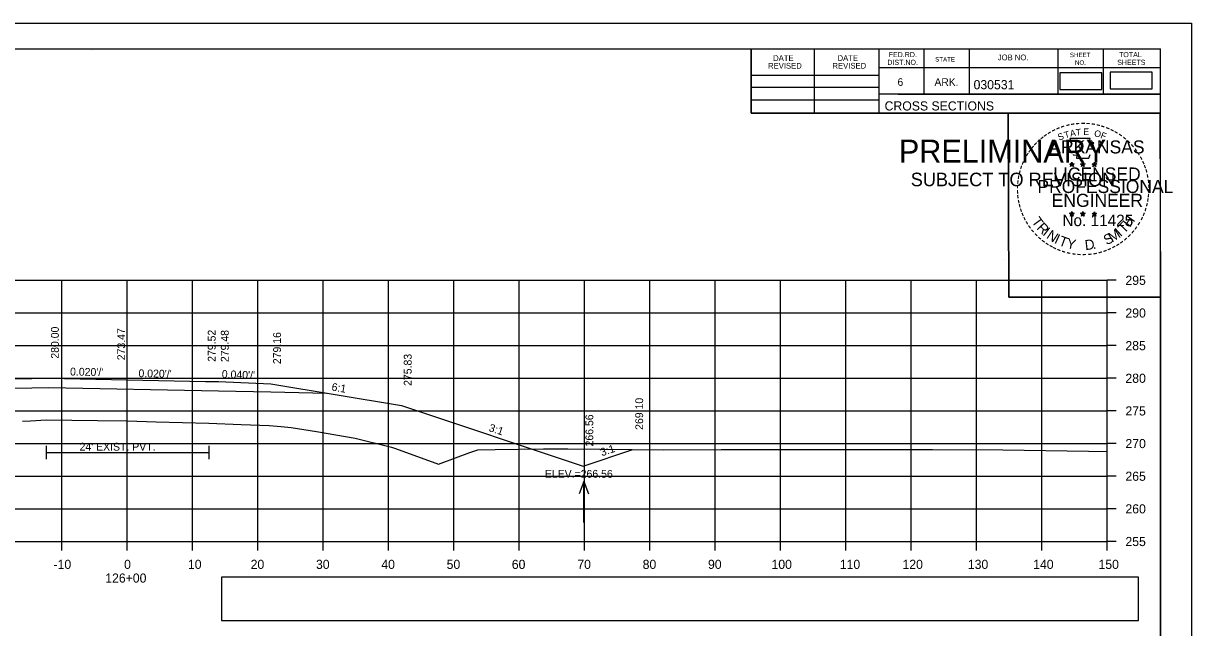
# Model space of a CAD drawing. Extents: x 285 to 4233, y -659 to 3710.
# Drawn here: x 2543.6 to 2722.4, y 1377 to 1469.5 of the extents above; entities that cross this region are included whole.
import ezdxf

# ---------------------------------------------------------------- set-up
doc = ezdxf.new("R2010")
doc.units = 0
for name, color, linetype in [('R_Alt Surface', 7, 'Continuous'), ('R_Axis', 7, 'Continuous'), ('R_Axis Annot', 7, 'Continuous'), ('R_Border', 7, 'Continuous'), ('R_Border PE', 7, 'Continuous'), ('R_Border Prem', 7, 'Continuous'), ('R_Exist Surface', 7, 'Continuous'), ('R_Fin Surface', 7, 'Continuous'), ('R_Grid', 7, 'Continuous'), ('R_No Plot', 7, 'Continuous'), ('R_Water', 7, 'Continuous'), ('R_Water Annot', 7, 'Continuous'), ('R_Xsect Elev', 7, 'Continuous'), ('R_Xsect Slope', 7, 'Continuous')]:
    doc.layers.add(name, color=color, linetype=linetype)

msp = doc.modelspace()

# ---------------------------------------------------------------- linework, layer by layer
at = {"layer": 'R_Alt Surface'}
for points in [[(2513.23, 1413.08), (2521.5, 1413.24), (2547.5, 1413.76), (2573.5, 1413.24), (2581.5, 1413.08), (2590.07, 1412.91)], [(2547.09, 1404.81), (2547.09, 1402.81)], [(2547.09, 1403.81), (2572.03, 1403.81)], [(2572.03, 1404.81), (2572.03, 1402.81)]]:
    msp.add_lwpolyline(points, dxfattribs=at)
at = {"layer": 'R_Axis'}
for p, q in [((2709.5, 1390.18), (2709.5, 1430.18)), ((2710.9, 1430.18), (2709.5, 1430.18)), ((2710.9, 1425.18), (2709.5, 1425.18)), ((2710.9, 1420.18), (2709.5, 1420.18)), ((2710.9, 1415.18), (2709.5, 1415.18)), ((2710.9, 1410.18), (2709.5, 1410.18)), ((2710.9, 1405.18), (2709.5, 1405.18)), ((2710.9, 1400.18), (2709.5, 1400.18)), ((2710.9, 1395.18), (2709.5, 1395.18)), ((2409.5, 1390.18), (2709.5, 1390.18)), ((2549.5, 1388.78), (2549.5, 1390.18)), ((2559.5, 1388.78), (2559.5, 1390.18)), ((2569.5, 1388.78), (2569.5, 1390.18)), ((2579.5, 1388.78), (2579.5, 1390.18)), ((2589.5, 1388.78), (2589.5, 1390.18)), ((2599.5, 1388.78), (2599.5, 1390.18)), ((2609.5, 1388.78), (2609.5, 1390.18)), ((2619.5, 1388.78), (2619.5, 1390.18)), ((2629.5, 1388.78), (2629.5, 1390.18)), ((2639.5, 1388.78), (2639.5, 1390.18)), ((2649.5, 1388.78), (2649.5, 1390.18)), ((2659.5, 1388.78), (2659.5, 1390.18)), ((2669.5, 1388.78), (2669.5, 1390.18)), ((2679.5, 1388.78), (2679.5, 1390.18)), ((2689.5, 1388.78), (2689.5, 1390.18)), ((2699.5, 1388.78), (2699.5, 1390.18)), ((2709.5, 1388.78), (2709.5, 1390.18)), ((2710.9, 1390.18), (2709.5, 1390.18))]:
    msp.add_line(p, q, dxfattribs=at)
at = {"layer": 'R_Axis Annot'}
for points in [[(2702.25, 1459.42), (2708.71, 1459.42), (2708.71, 1461.98), (2702.25, 1461.98)], [(2709.94, 1459.49), (2716.4, 1459.49), (2716.4, 1462.05), (2709.94, 1462.05)], [(2573.96, 1378.07), (2714.32, 1378.07), (2714.32, 1384.72), (2573.96, 1384.72)]]:
    msp.add_lwpolyline(points, close=True, dxfattribs=at)
at = {"layer": 'R_Border'}
for p, q in [((2401.5, 1465.64), (2717.68, 1465.64)), ((2554.02, 1465.38), (2554.02, 1465.38)), ((2554.02, 1465.38), (2554.02, 1465.38)), ((2655.04, 1455.76), (2655.04, 1465.64)), ((2664.72, 1455.76), (2664.72, 1465.64)), ((2674.58, 1465.64), (2674.58, 1455.76)), ((2681.42, 1465.64), (2681.42, 1458.7)), ((2688.36, 1465.64), (2688.36, 1458.7)), ((2701.94, 1465.64), (2701.94, 1458.7)), ((2708.88, 1465.64), (2708.88, 1458.7)), ((2717.68, 1260.18), (2717.68, 1465.64)), ((2717.68, 1462.7), (2674.58, 1462.7)), ((2717.68, 1462.72), (2717.68, 1462.72)), ((2655.04, 1461.62), (2674.58, 1461.62)), ((2655.04, 1459.76), (2674.58, 1459.76)), ((2655.04, 1457.82), (2674.58, 1457.82)), ((2717.68, 1458.7), (2674.58, 1458.7)), ((2677.54, 1458.7), (2717.68, 1458.7)), ((2717.68, 1455.76), (2655.04, 1455.76))]:
    msp.add_line(p, q, dxfattribs=at)
at = {"layer": 'R_Border PE'}
for p, q in [((2703.77, 1448.02), (2704.11, 1447.9)), ((2703.77, 1448.02), (2704.02, 1447.97)), ((2703.77, 1448.02), (2704, 1447.89)), ((2703.9, 1447.61), (2704.11, 1447.9)), ((2703.9, 1447.61), (2704.02, 1447.85)), ((2703.9, 1447.61), (2704.11, 1447.82)), ((2704.11, 1448.27), (2704.07, 1448.02)), ((2704.11, 1447.9), (2704.11, 1448.27)), ((2704.11, 1448.27), (2704.16, 1448.02)), ((2704.46, 1448.02), (2704.11, 1447.9)), ((2704.33, 1447.61), (2704.11, 1447.9)), ((2704.33, 1447.61), (2704.11, 1447.82)), ((2704.46, 1448.02), (2704.18, 1447.97)), ((2704.33, 1447.61), (2704.19, 1447.9)), ((2704.46, 1448.02), (2704.26, 1447.91)), ((2705.44, 1448.02), (2705.78, 1447.9)), ((2705.44, 1448.02), (2705.69, 1447.97)), ((2705.44, 1448.02), (2705.67, 1447.89)), ((2705.57, 1447.61), (2705.78, 1447.9)), ((2705.57, 1447.61), (2705.69, 1447.85)), ((2705.57, 1447.61), (2705.78, 1447.82)), ((2705.78, 1448.27), (2705.74, 1448.02)), ((2705.78, 1447.9), (2705.78, 1448.27)), ((2705.78, 1448.27), (2705.83, 1448.02)), ((2706.13, 1448.02), (2705.78, 1447.9)), ((2706, 1447.61), (2705.78, 1447.9)), ((2706, 1447.61), (2705.78, 1447.82)), ((2706.13, 1448.02), (2705.85, 1447.97)), ((2706, 1447.61), (2705.86, 1447.9)), ((2706.13, 1448.02), (2705.93, 1447.91)), ((2707.2, 1448), (2707.55, 1447.89)), ((2707.2, 1448), (2707.45, 1447.96)), ((2707.2, 1448), (2707.44, 1447.88)), ((2707.33, 1447.6), (2707.55, 1447.89)), ((2707.33, 1447.6), (2707.46, 1447.84)), ((2707.33, 1447.6), (2707.55, 1447.81)), ((2707.55, 1448.26), (2707.51, 1448.01)), ((2707.55, 1447.89), (2707.55, 1448.26)), ((2707.55, 1448.26), (2707.6, 1448.01)), ((2707.9, 1448), (2707.55, 1447.89)), ((2707.76, 1447.6), (2707.55, 1447.89)), ((2707.76, 1447.6), (2707.55, 1447.81)), ((2707.9, 1448), (2707.61, 1447.95)), ((2707.76, 1447.6), (2707.62, 1447.89)), ((2707.9, 1448), (2707.69, 1447.9)), ((2703.76, 1440.44), (2704.11, 1440.33)), ((2703.76, 1440.44), (2704.01, 1440.4)), ((2703.76, 1440.44), (2704, 1440.32)), ((2703.89, 1440.03), (2704.11, 1440.33)), ((2703.89, 1440.03), (2704.02, 1440.28)), ((2703.89, 1440.03), (2704.11, 1440.25)), ((2704.11, 1440.7), (2704.07, 1440.44)), ((2704.11, 1440.33), (2704.11, 1440.7)), ((2704.11, 1440.7), (2704.16, 1440.45)), ((2704.46, 1440.44), (2704.11, 1440.33)), ((2704.32, 1440.03), (2704.11, 1440.33)), ((2704.32, 1440.03), (2704.11, 1440.25)), ((2704.46, 1440.44), (2704.17, 1440.39)), ((2704.32, 1440.03), (2704.19, 1440.33)), ((2704.46, 1440.44), (2704.25, 1440.34)), ((2705.43, 1440.44), (2705.78, 1440.33)), ((2705.43, 1440.44), (2705.68, 1440.4)), ((2705.43, 1440.44), (2705.67, 1440.32)), ((2705.56, 1440.03), (2705.78, 1440.33)), ((2705.56, 1440.03), (2705.69, 1440.28)), ((2705.56, 1440.03), (2705.78, 1440.25)), ((2705.78, 1440.7), (2705.74, 1440.44)), ((2705.78, 1440.33), (2705.78, 1440.7)), ((2705.78, 1440.7), (2705.83, 1440.45)), ((2706.13, 1440.44), (2705.78, 1440.33)), ((2705.99, 1440.03), (2705.78, 1440.33)), ((2705.99, 1440.03), (2705.78, 1440.25)), ((2706.13, 1440.44), (2705.84, 1440.39)), ((2705.99, 1440.03), (2705.86, 1440.33)), ((2706.13, 1440.44), (2705.92, 1440.34)), ((2707.2, 1440.43), (2707.55, 1440.32)), ((2707.2, 1440.43), (2707.45, 1440.39)), ((2707.2, 1440.43), (2707.43, 1440.31)), ((2707.33, 1440.02), (2707.55, 1440.32)), ((2707.33, 1440.02), (2707.46, 1440.27)), ((2707.33, 1440.02), (2707.54, 1440.24)), ((2707.55, 1440.69), (2707.51, 1440.43)), ((2707.76, 1440.02), (2707.54, 1440.24)), ((2707.55, 1440.32), (2707.55, 1440.69)), ((2707.55, 1440.69), (2707.6, 1440.44)), ((2707.89, 1440.43), (2707.55, 1440.32)), ((2707.76, 1440.02), (2707.55, 1440.32)), ((2707.89, 1440.43), (2707.61, 1440.38)), ((2707.76, 1440.02), (2707.62, 1440.32)), ((2707.89, 1440.43), (2707.69, 1440.33))]:
    msp.add_line(p, q, dxfattribs=at)
for points in [[(2703.81, 1451.89), (2704.08, 1451.07)], [(2707.32, 1450.97), (2707.46, 1451.26), (2706.77, 1451.23), (2706.92, 1451.89), (2703.81, 1451.89)], [(2704.3, 1449.47), (2704.3, 1449.38), (2704.86, 1449.36), (2704.81, 1448.89), (2706.68, 1448.89), (2706.88, 1449.43)], [(2704.11, 1448.27), (2704.33, 1447.61), (2703.77, 1448.02), (2704.46, 1448.02), (2703.9, 1447.61), (2704.11, 1448.27)], [(2705.78, 1448.27), (2706, 1447.61), (2705.44, 1448.02), (2706.13, 1448.02), (2705.57, 1447.61), (2705.78, 1448.27)], [(2707.55, 1448.26), (2707.76, 1447.6), (2707.2, 1448), (2707.9, 1448), (2707.33, 1447.6), (2707.55, 1448.26)], [(2704.11, 1440.7), (2704.32, 1440.03), (2703.76, 1440.44), (2704.46, 1440.44), (2703.89, 1440.03), (2704.11, 1440.7)], [(2705.78, 1440.7), (2705.99, 1440.03), (2705.43, 1440.44), (2706.13, 1440.44), (2705.56, 1440.03), (2705.78, 1440.7)], [(2707.55, 1440.69), (2707.76, 1440.02), (2707.2, 1440.43), (2707.89, 1440.43), (2707.33, 1440.02), (2707.55, 1440.69)]]:
    msp.add_lwpolyline(points, dxfattribs=at)
for centre, radius in [((2704.11, 1447.9), 0.172), ((2704.11, 1447.9), 0.145), ((2704.11, 1447.9), 0.116), ((2704.11, 1447.9), 0.0991), ((2704.11, 1447.9), 0.0747), ((2704.11, 1447.9), 0.0495), ((2704.11, 1447.9), 0.0296), ((2705.78, 1447.9), 0.172), ((2705.78, 1447.9), 0.145), ((2705.78, 1447.9), 0.116), ((2705.78, 1447.9), 0.0991), ((2705.78, 1447.9), 0.0747), ((2705.78, 1447.9), 0.0495), ((2705.78, 1447.9), 0.0296), ((2707.55, 1447.89), 0.172), ((2707.55, 1447.89), 0.145), ((2707.55, 1447.89), 0.116), ((2707.55, 1447.89), 0.0991), ((2707.55, 1447.89), 0.0747), ((2707.55, 1447.89), 0.0495), ((2707.55, 1447.89), 0.0296), ((2704.11, 1440.33), 0.172), ((2704.11, 1440.33), 0.145), ((2704.11, 1440.33), 0.116), ((2704.11, 1440.33), 0.0991), ((2704.11, 1440.33), 0.0747), ((2704.11, 1440.33), 0.0495), ((2704.11, 1440.33), 0.0296), ((2705.78, 1440.33), 0.172), ((2705.78, 1440.33), 0.145), ((2705.78, 1440.33), 0.116), ((2705.78, 1440.33), 0.0991), ((2705.78, 1440.33), 0.0747), ((2705.78, 1440.33), 0.0495), ((2705.78, 1440.33), 0.0296), ((2707.55, 1440.32), 0.172), ((2707.55, 1440.32), 0.145), ((2707.55, 1440.32), 0.116), ((2707.55, 1440.32), 0.0991), ((2707.55, 1440.32), 0.0747), ((2707.55, 1440.32), 0.0495), ((2707.55, 1440.32), 0.0296)]:
    msp.add_circle(centre, radius, dxfattribs=at)
at = {"layer": 'R_Exist Surface'}
msp.add_lwpolyline([(2543.51, 1408.62), (2544.69, 1408.68), (2547.09, 1408.81), (2554.98, 1408.71), (2559.51, 1408.65), (2563.95, 1408.52), (2572.03, 1408.3), (2576.94, 1408.1), (2581.22, 1407.94), (2583.1, 1407.79), (2584.61, 1407.65), (2588.51, 1407.02), (2594.41, 1406.02), (2599.98, 1404.61), (2600.26, 1404.54), (2600.59, 1404.42), (2607.15, 1402.02), (2611.98, 1403.79), (2613.18, 1404.23), (2615.83, 1404.26), (2623.24, 1404.35), (2626.98, 1404.36), (2641.66, 1404.24), (2650.44, 1404.28), (2660.08, 1404.27), (2676.93, 1404.29), (2682.78, 1404.26), (2693.53, 1404.21), (2706.66, 1403.99), (2709.5, 1403.96)], dxfattribs=at)
at = {"layer": 'R_Fin Surface'}
msp.add_lwpolyline([(2489.43, 1408.73), (2494.81, 1406.94), (2517.5, 1414.5), (2521.5, 1414.66), (2547.5, 1415.18), (2571.5, 1414.7), (2573.5, 1414.66), (2581.5, 1414.34), (2601.5, 1411.01), (2629.3, 1401.74), (2636.93, 1404.28)], dxfattribs=at)
at = {"layer": 'R_Grid'}
for p, q in [((2409.5, 1430.18), (2709.5, 1430.18)), ((2549.5, 1390.18), (2549.5, 1430.18)), ((2559.5, 1390.18), (2559.5, 1430.18)), ((2569.5, 1390.18), (2569.5, 1430.18)), ((2579.5, 1390.18), (2579.5, 1430.18)), ((2589.5, 1390.18), (2589.5, 1430.18)), ((2599.5, 1390.18), (2599.5, 1430.18)), ((2609.5, 1390.18), (2609.5, 1430.18)), ((2619.5, 1390.18), (2619.5, 1430.18)), ((2629.5, 1390.18), (2629.5, 1430.18)), ((2639.5, 1390.18), (2639.5, 1430.18)), ((2649.5, 1390.18), (2649.5, 1430.18)), ((2659.5, 1390.18), (2659.5, 1430.18)), ((2669.5, 1390.18), (2669.5, 1430.18)), ((2679.5, 1390.18), (2679.5, 1430.18)), ((2689.5, 1390.18), (2689.5, 1430.18)), ((2699.5, 1390.18), (2699.5, 1430.18)), ((2709.5, 1390.18), (2709.5, 1430.18)), ((2409.5, 1425.18), (2709.5, 1425.18)), ((2409.5, 1420.18), (2709.5, 1420.18)), ((2409.5, 1415.18), (2709.5, 1415.18)), ((2409.5, 1410.18), (2709.5, 1410.18)), ((2409.5, 1405.18), (2709.5, 1405.18)), ((2409.5, 1400.18), (2709.5, 1400.18)), ((2409.5, 1395.18), (2709.5, 1395.18)), ((2409.5, 1390.18), (2709.5, 1390.18))]:
    msp.add_line(p, q, dxfattribs=at)
at = {"layer": 'R_No Plot'}
for p, q in [((2389.1, 1469.54), (2722.43, 1469.54)), ((2693.72, 1433.3), (2693.72, 1433.3))]:
    msp.add_line(p, q, dxfattribs=at)
for points in [[(2389.09, 1469.54), (2722.43, 1469.54), (2722.43, 1256.2), (2389.09, 1256.2)], [(2635.42, 1465.64), (2655.04, 1465.64), (2655.04, 1455.76), (2671.15, 1455.76), (2694.35, 1455.76), (2694.47, 1427.6), (2717.68, 1427.6), (2717.68, 1260.18), (2401.5, 1260.18), (2401.5, 1465.64)], [(2694.35, 1455.76), (2717.56, 1455.76), (2717.68, 1427.6), (2694.47, 1427.6)]]:
    msp.add_lwpolyline(points, close=True, dxfattribs=at)
at = {"layer": 'R_Water Annot'}
for p, q in [((2629.4, 1399.39), (2628.7, 1397.47)), ((2629.4, 1393.11), (2629.4, 1399.39)), ((2629.4, 1399.39), (2630.1, 1397.47))]:
    msp.add_line(p, q, dxfattribs=at)
at = {"layer": 'R_Xsect Elev'}
msp.add_line((2559.5, 1408.65), (2559.5, 1423.87), dxfattribs=at)

# ---------------------------------------------------------------- texts
at = {"layer": 'R_Axis Annot'}
for s, p in [('295', (2712.3, 1429.48)), ('290', (2712.3, 1424.48)), ('285', (2712.3, 1419.48)), ('280', (2712.3, 1414.48)), ('275', (2712.3, 1409.48)), ('270', (2712.3, 1404.48)), ('265', (2712.3, 1399.48)), ('260', (2712.3, 1394.48)), ('255', (2712.3, 1389.48)), ('-10', (2548.24, 1385.98)), ('0', (2559.04, 1385.98)), ('10', (2568.81, 1385.98)), ('20', (2578.41, 1385.98)), ('30', (2588.41, 1385.98)), ('40', (2598.41, 1385.98)), ('50', (2608.41, 1385.98)), ('60', (2618.38, 1385.98)), ('70', (2628.41, 1385.98)), ('80', (2638.41, 1385.98)), ('90', (2648.41, 1385.98)), ('100', (2658.13, 1385.98)), ('110', (2668.58, 1385.98)), ('120', (2678.18, 1385.98)), ('130', (2688.18, 1385.98)), ('140', (2698.18, 1385.98)), ('150', (2708.18, 1385.98)), ('126+00', (2556.16, 1383.88))]:
    msp.add_text(s, height=1.4, dxfattribs=at).set_placement(p)
at = {"layer": 'R_Border'}
for s, height, p in [('DATE', 0.879, (2658.38, 1463.78)), ('DATE', 0.879, (2668.24, 1463.78)), ('FED.RD.', 0.782, (2676.06, 1464.36)), ('JOB NO.', 0.879, (2692.76, 1463.88)), ('SHEET', 0.684, (2703.8, 1464.36)), ('TOTAL', 0.782, (2711.32, 1464.36)), ('REVISED', 0.879, (2657.6, 1462.6)), ('REVISED', 0.879, (2667.46, 1462.6)), ('DIST.NO.', 0.782, (2675.86, 1463.18)), ('STATE', 0.684, (2683.18, 1463.68)), ('NO.', 0.684, (2704.58, 1463.18)), ('SHEETS', 0.782, (2711.04, 1463.18)), ('6', 1.17, (2677.42, 1459.96)), ('ARK.', 1.172, (2683.08, 1459.96)), ('030531', 1.4, (2689.06, 1459.44)), ('CROSS SECTIONS', 1.4, (2675.44, 1456.19))]:
    msp.add_text(s, height=height, rotation=360, dxfattribs=at).set_placement(p)
at = {"layer": 'R_Border PE'}
for s, height, rotation, p in [('-', 1.6, 19.1761, (2702.55, 1453.02)), ('-', 1.6, 13.6301, (2703.3, 1453.26)), ('-', 1.6, 10.2193, (2703.98, 1453.42)), ('-', 1.6, 5.8968, (2704.71, 1453.53)), ('-', 1.6, 0.1862, (2705.48, 1453.61)), ('-', 1.6, 357.743, (2706.21, 1453.59)), ('-', 1.6, 352.1617, (2706.95, 1453.54)), ('-', 1.6, 347.2049, (2707.67, 1453.42)), ('-', 1.6, 342.3362, (2708.3, 1453.27)), ('-', 1.6, 38.9507, (2699.64, 1451.29)), ('-', 1.6, 36.2317, (2700.11, 1451.67)), ('-', 1.6, 34.0636, (2700.69, 1452.06)), ('-', 1.6, 28.7918, (2701.29, 1452.43)), ('-', 1.6, 24.3072, (2701.92, 1452.75)), ('S', 1, 21.594, (2702.16, 1451.57)), ('T', 1, 16.4036, (2703.08, 1451.9)), ('A', 1, 11.2132, (2703.9, 1452.15)), ('T', 1, 6.0228, (2704.75, 1452.32)), ('E', 1, 0.8323, (2705.86, 1452.43)), ('O', 1, 350.4515, (2707.46, 1452.22)), ('F', 1, 340.0707, (2708.41, 1451.99)), ('-', 1.6, 337.8551, (2709.04, 1453.04)), ('-', 1.6, 334.1211, (2709.67, 1452.77)), ('-', 1.6, 329.6409, (2710.25, 1452.49)), ('-', 1.6, 325.8627, (2710.89, 1452.13)), ('-', 1.6, 320.5297, (2711.5, 1451.7)), ('-', 1.6, 54.2325, (2697.94, 1449.34)), ('-', 1.6, 50.6142, (2698.35, 1449.91)), ('-', 1.6, 48.423, (2698.76, 1450.4)), ('-', 1.6, 42.9622, (2699.2, 1450.87)), ('ARKANSAS', 2, 360, (2700.66, 1449.61)), ('-', 1.6, 315.5786, (2712.1, 1451.22)), ('-', 1.6, 309.8797, (2712.67, 1450.67)), ('-', 1.6, 306.6522, (2713.2, 1450.06)), ('-', 1.6, 67.7743, (2697.04, 1447.59)), ('-', 1.6, 62.8713, (2697.3, 1448.2)), ('-', 1.6, 58.0706, (2697.61, 1448.82)), ('-', 1.4, 303.6753, (2713.68, 1449.5)), ('-', 1.6, 299.6684, (2714, 1448.89)), ('-', 1.6, 294.6628, (2714.32, 1448.28)), ('-', 1.6, 75.461, (2696.63, 1446.25)), ('-', 1.6, 72.3945, (2696.82, 1446.96)), ('LICENSED', 2, 360, (2701.26, 1445.46)), ('DWB', 0.01, 360, (2704.1, 1447.9)), ('DWB', 0.01, 360, (2705.77, 1447.9)), ('DWB', 0.01, 360, (2707.54, 1447.89)), ('-', 1.6, 290.5728, (2714.58, 1447.7)), ('-', 1.6, 285.1233, (2714.82, 1447.12)), ('-', 1.6, 85.1863, (2696.42, 1444.84)), ('-', 1.6, 81.2013, (2696.49, 1445.53)), ('PROFESSIONAL', 2, 360, (2698.83, 1443.55)), ('-', 1.6, 280.5493, (2715.02, 1446.38)), ('-', 1.6, 276.5962, (2715.18, 1445.61)), ('-', 1.6, 274.3301, (2715.24, 1444.89)), ('-', 1.6, 94.1959, (2696.43, 1443.42)), ('-', 1.6, 89.0622, (2696.39, 1444.14)), ('-', 1.6, 98.9479, (2696.5, 1442.75)), ('ENGINEER', 2, 360, (2701.02, 1441.43)), ('-', 1.6, 263.5172, (2715.25, 1443.59)), ('-', 1.6, 269.9407, (2715.27, 1444.26)), ('-', 1.6, 101.7149, (2696.64, 1442.02)), ('-', 1.6, 105.4578, (2696.8, 1441.42)), ('-', 1.6, 252.8681, (2714.89, 1441.54)), ('-', 1.6, 255.7626, (2715.07, 1442.26)), ('-', 1.6, 260.9953, (2715.18, 1442.94)), ('-', 1.6, 109.0874, (2697.01, 1440.79)), ('-', 1.6, 114.0643, (2697.27, 1440.2)), ('-', 1.6, 115.7289, (2697.57, 1439.58)), ('T', 1.54, 306.0406, (2697.87, 1439.17)), ('No. 11425', 1.757, 360, (2702.65, 1438.48)), ('DWB', 0.01, 360, (2704.1, 1440.33)), ('DWB', 0.01, 360, (2705.77, 1440.33)), ('DWB', 0.01, 360, (2707.53, 1440.32)), ('H', 1.54, 54.6088, (2712.99, 1438.2)), ('-', 1.6, 244.6197, (2714.41, 1440.24)), ('-', 1.6, 247.8887, (2714.67, 1440.86)), ('-', 1.6, 120.4471, (2697.93, 1438.99)), ('-', 1.6, 125.8934, (2698.33, 1438.43)), ('-', 1.6, 130.7181, (2698.79, 1437.88)), ('R', 1.54, 314.005, (2698.63, 1438.12)), ('I', 1.54, 321.9694, (2699.53, 1437.19)), ('N', 1.54, 326.5002, (2700.1, 1436.72)), ('M', 1.54, 32.6563, (2710.26, 1435.94)), ('I', 1.54, 42.1136, (2711.54, 1436.78)), ('T', 1.54, 46.6444, (2712.1, 1437.26)), ('-', 1.6, 231.2538, (2713.18, 1438.26)), ('-', 1.6, 233.8452, (2713.61, 1438.83)), ('-', 1.6, 239.0712, (2714.01, 1439.48)), ('-', 1.6, 134.2238, (2699.31, 1437.33)), ('-', 1.6, 138.9338, (2699.84, 1436.87)), ('-', 1.6, 144.6463, (2700.39, 1436.46)), ('-', 1.6, 148.0898, (2700.95, 1436.09)), ('I', 1.54, 335.3603, (2701.31, 1435.93)), ('T', 1.54, 339.8912, (2701.97, 1435.6)), ('Y', 1.54, 347.8556, (2703.19, 1435.16)), ('D', 1.54, 6.3969, (2706.17, 1434.8)), ('S', 1.54, 26.9312, (2709.42, 1435.53)), ('-', 1.6, 215.7363, (2711.63, 1436.72)), ('-', 1.6, 221.0851, (2712.18, 1437.19)), ('-', 1.6, 225.7653, (2712.7, 1437.7)), ('-', 1.6, 151.5704, (2701.53, 1435.77)), ('-', 1.6, 154.6002, (2702.05, 1435.52)), ('-', 1.6, 158.5612, (2702.68, 1435.27)), ('-', 1.6, 162.7983, (2703.36, 1435.05)), ('-', 1.6, 167.5555, (2704.08, 1434.89)), ('-', 1.6, 173.1155, (2704.85, 1434.78)), ('-', 1.6, 176.5183, (2705.6, 1434.73)), ('-', 1.6, 181.5918, (2706.34, 1434.75)), ('-', 1.6, 185.8167, (2707.15, 1434.82)), ('-', 1.6, 191.2858, (2707.89, 1434.95)), ('.', 1.54, 13.7642, (2707.36, 1434.93)), ('-', 1.6, 195.4743, (2708.62, 1435.15)), ('-', 1.6, 200.7184, (2709.29, 1435.39)), ('-', 1.6, 204.2516, (2709.91, 1435.67)), ('-', 1.6, 207.3568, (2710.54, 1435.99)), ('-', 1.6, 212.2491, (2711.1, 1436.33))]:
    msp.add_text(s, height=height, rotation=rotation, dxfattribs=at).set_placement(p)
at = {"layer": 'R_Border Prem'}
for s, height, p in [('PRELIMINARY', 3.5, (2677.63, 1448.22)), ('DWB', 0.01, (2678.38, 1450.07)), ('SUBJECT TO REVISION', 2.0751, (2679.44, 1444.59))]:
    msp.add_text(s, height=height, rotation=360, dxfattribs=at).set_placement(p)
at = {"layer": 'R_Water'}
msp.add_text("24' EXIST. PVT.", height=1.2, dxfattribs=at).set_placement((2552.22, 1404.09))
at = {"layer": 'R_Xsect Elev'}
for s, p in [('280.00', (2549.05, 1418.18)), ('273.47', (2559.2, 1417.94)), ('279.52', (2573.05, 1417.7)), ('279.48', (2575.05, 1417.66)), ('279.16', (2583.05, 1417.34)), ('275.83', (2603.05, 1414.01)), ('269.10', (2638.48, 1407.28)), ('266.56', (2630.85, 1404.74))]:
    msp.add_text(s, height=1.2, rotation=90, dxfattribs=at).set_placement(p)
msp.add_text('ELEV.=266.56', height=1.2, dxfattribs=at).set_placement((2623.44, 1399.94))
at = {"layer": 'R_Xsect Slope'}
for s, rotation, p in [("0.020'/'", 358.8542, (2550.76, 1415.61)), ("0.020'/'", 358.8542, (2561.23, 1415.35)), ("0.040'/'", 357.7094, (2573.97, 1415.24)), ('6:1', 350.5377, (2590.73, 1413.31)), ('3:1', 341.5651, (2614.77, 1407.11)), ('3:1', 18.4349, (2632.17, 1403.22))]:
    msp.add_text(s, height=1.2, rotation=rotation, dxfattribs=at).set_placement(p)

doc.saveas('drawing.dxf')
